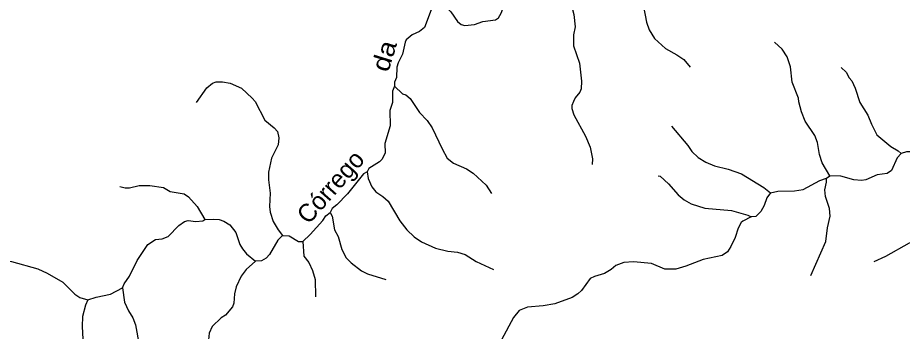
# Model space of a CAD drawing. Extents: x 577 to 602.9, y 7483.8 to 7511.6.
# Drawn here: x 595.283 to 599.238, y 7502.644 to 7504.044 of the extents above; entities that cross this region are included whole.
import ezdxf
from ezdxf.enums import TextEntityAlignment as Align

# ---------------------------------------------------------------- set-up
doc = ezdxf.new("R2010")
doc.units = 0
doc.header["$LTSCALE"] = 0.032
doc.layers.add('61', color=7, linetype='Continuous')
doc.layers.add('7', color=7, linetype='Continuous', lineweight=25)

msp = doc.modelspace()

# ---------------------------------------------------------------- linework, layer by layer
at = {"layer": '7'}
for points in [[(598.1262, 7504.3943), (598.1131, 7504.3706), (598.1057, 7504.3477), (598.1025, 7504.2978), (598.0976, 7504.2749), (598.0861, 7504.2471), (598.0673, 7504.2226), (598.0518, 7504.194), (598.0485, 7504.185), (598.0485, 7504.1597), (598.0812, 7504.0951), (598.0943, 7504.0248), (598.1065, 7503.9905), (598.1303, 7503.9521), (598.1793, 7503.9063), (598.23, 7503.8793), (598.261, 7503.8572), (598.2899, 7503.8234)], [(597.1322, 7504.0796), (597.1698, 7504.0976), (597.1919, 7504.0976), (597.2197, 7504.0714), (597.2491, 7504.0281), (597.2654, 7504.0142), (597.2818, 7504.0093), (597.3259, 7504.0142), (597.3627, 7504.0281), (597.4199, 7504.0346), (597.4322, 7504.0436), (597.4444, 7504.0641), (597.4722, 7504.1401), (597.5008, 7504.1744), (597.536, 7504.1973), (597.5785, 7504.2185), (597.5989, 7504.2234), (597.6488, 7504.2243), (597.6627, 7504.2283), (597.6799, 7504.2382), (597.7248, 7504.2782), (597.7403, 7504.2839)], [(597.7403, 7504.2839), (597.7395, 7504.2635), (597.7314, 7504.2316), (597.7314, 7504.2014), (597.7518, 7504.1589), (597.7592, 7504.0984), (597.769, 7504.0591), (597.7747, 7504.0036), (597.7681, 7503.9676), (597.7673, 7503.9194), (597.7951, 7503.8409), (597.8041, 7503.7616), (597.8017, 7503.7265), (597.7959, 7503.7126), (597.7755, 7503.6872), (597.7673, 7503.6709), (597.7608, 7503.6521), (597.7608, 7503.639), (597.769, 7503.6104), (597.8213, 7503.5156), (597.8425, 7503.4657), (597.8532, 7503.415), (597.852, 7503.3885)], [(597.1322, 7504.0796), (597.102, 7504.0003), (597.0791, 7503.9831), (597.0472, 7503.9684), (597.0202, 7503.9455), (597.0153, 7503.9357), (597.0039, 7503.881), (596.9842, 7503.8434), (596.9785, 7503.8237), (596.9761, 7503.778), (596.9679, 7503.7559), (596.9671, 7503.7387)], [(598.9141, 7503.3382), (598.879, 7503.3962), (598.8676, 7503.433), (598.8594, 7503.4878), (598.8463, 7503.518), (598.803, 7503.5826), (598.7866, 7503.6243), (598.7752, 7503.6684), (598.7736, 7503.6848), (598.7449, 7503.7559), (598.7376, 7503.8254), (598.7237, 7503.8695), (598.7008, 7503.9047), (598.6666, 7503.9345)], [(598.9647, 7503.8222), (598.9861, 7503.8008), (599.0008, 7503.7763), (599.0122, 7503.7632), (599.0278, 7503.7297), (599.0482, 7503.666), (599.0833, 7503.6096), (599.0997, 7503.5687), (599.1242, 7503.5221), (599.1863, 7503.4698), (599.2199, 7503.4502), (599.2329, 7503.4379)], [(596.0828, 7503.6659), (596.1284, 7503.7314), (596.1538, 7503.7518), (596.1701, 7503.7575), (596.1987, 7503.7575), (596.2331, 7503.7518), (596.2837, 7503.7297), (596.332, 7503.6848), (596.3442, 7503.6701), (596.3875, 7503.5867), (596.43, 7503.5532), (596.4448, 7503.5368), (596.4513, 7503.5074), (596.448, 7503.4772), (596.4178, 7503.4167), (596.4039, 7503.3545), (596.4039, 7503.3202), (596.4121, 7503.2605), (596.4096, 7503.2009), (596.4112, 7503.1763), (596.4251, 7503.1338), (596.4472, 7503.0979), (596.4676, 7503.0725)], [(596.9671, 7503.7387), (596.9581, 7503.7167), (596.9589, 7503.6652), (596.9466, 7503.63), (596.9483, 7503.5622), (596.9246, 7503.4821), (596.9254, 7503.4396), (596.9115, 7503.4118), (596.9009, 7503.4011), (596.8535, 7503.3709), (596.8453, 7503.357)], [(596.9671, 7503.7387), (597.0039, 7503.7052), (597.0186, 7503.6995), (597.0374, 7503.6831), (597.0799, 7503.6218), (597.1134, 7503.5859), (597.1363, 7503.5532), (597.1804, 7503.4592), (597.2033, 7503.4167), (597.2319, 7503.3946), (597.29, 7503.3701), (597.3194, 7503.3496), (597.3774, 7503.2973), (597.4007, 7503.2598)], [(599.7365, 7503.6161), (599.707, 7503.603), (599.6163, 7503.594), (599.5893, 7503.5867), (599.5713, 7503.5769), (599.5566, 7503.5622), (599.5509, 7503.5483), (599.5468, 7503.5295), (599.5452, 7503.4788), (599.5386, 7503.4665), (599.5215, 7503.4543), (599.5051, 7503.4518), (599.4651, 7503.46), (599.4438, 7503.4584), (599.4209, 7503.4518), (599.3817, 7503.4306), (599.3539, 7503.424), (599.2722, 7503.4461), (599.2563, 7503.4449), (599.2329, 7503.4379)], [(598.2053, 7503.5604), (598.279, 7503.4739), (598.297, 7503.4469), (598.3256, 7503.4199), (598.3591, 7503.3995), (598.3984, 7503.3832), (598.4589, 7503.3684), (598.5193, 7503.3472), (598.6191, 7503.2867), (598.6485, 7503.2622)], [(599.2329, 7503.4379), (599.215, 7503.4191), (599.1888, 7503.3627), (599.17, 7503.3488), (599.1259, 7503.3423), (599.0744, 7503.321), (599.0547, 7503.3178), (599.0204, 7503.321), (598.9632, 7503.3366), (598.9141, 7503.3382)], [(596.8453, 7503.357), (596.8289, 7503.348), (596.7578, 7503.2573), (596.7096, 7503.2082), (596.6892, 7503.1927), (596.6794, 7503.1747)], [(596.8453, 7503.357), (596.8502, 7503.3267), (596.8657, 7503.2891), (596.8845, 7503.2663), (596.9156, 7503.2466), (596.9401, 7503.2246), (596.9916, 7503.1379), (597.0235, 7503.0971), (597.0562, 7503.066), (597.0889, 7503.0439), (597.151, 7503.0153), (597.2066, 7503.0022), (597.2499, 7502.9973), (597.2842, 7502.9875), (597.3325, 7502.9565), (597.4096, 7502.9205)], [(598.147, 7503.3383), (598.1548, 7503.3366), (598.1924, 7503.303), (598.2357, 7503.254), (598.2627, 7503.2311), (598.2937, 7503.2131), (598.355, 7503.1935), (598.4744, 7503.1837), (598.5479, 7503.1633), (598.5618, 7503.1551)], [(598.6485, 7503.2622), (598.682, 7503.2695), (598.7564, 7503.2712), (598.794, 7503.2777), (598.8684, 7503.3178), (598.8994, 7503.3276)], [(598.8283, 7502.8939), (598.8953, 7503.0447), (598.9035, 7503.1069), (598.915, 7503.1584), (598.9117, 7503.1927), (598.8937, 7503.2466), (598.8921, 7503.2753), (598.8994, 7503.3104), (598.8994, 7503.3276), (598.9141, 7503.3382)], [(595.7395, 7503.2914), (595.7639, 7503.2851), (595.7835, 7503.2851), (595.826, 7503.2957), (595.8742, 7503.2949), (595.9347, 7503.2859), (595.9649, 7503.2679), (596.0279, 7503.2573), (596.0475, 7503.245), (596.0859, 7503.2017), (596.1194, 7503.1428)], [(598.6485, 7503.2622), (598.6321, 7503.2409), (598.6207, 7503.2066), (598.6052, 7503.1788), (598.5831, 7503.1575), (598.5618, 7503.1551)], [(595.7524, 7502.8379), (595.7598, 7502.8567), (595.7835, 7502.8903), (595.8178, 7502.9597), (595.8644, 7503.0317), (595.8995, 7503.0537), (595.9298, 7503.0578), (595.956, 7503.0676), (596.0042, 7503.1159), (596.0295, 7503.1338), (596.045, 7503.1387), (596.0802, 7503.1347), (596.1104, 7503.1379), (596.1194, 7503.1428)], [(596.1194, 7503.1428), (596.1587, 7503.1453), (596.1832, 7503.1428), (596.2044, 7503.1363), (596.2322, 7503.1199), (596.2584, 7503.0848), (596.2764, 7503.0325), (596.2886, 7503.0129), (596.3066, 7502.9908), (596.3467, 7502.9573)], [(596.5576, 7503.0447), (596.5903, 7503.0758), (596.6475, 7503.1396), (596.6614, 7503.16), (596.6794, 7503.1747)], [(596.6794, 7503.1747), (596.6892, 7503.1584), (596.6998, 7503.0971), (596.7153, 7503.0668), (596.7325, 7503.0088), (596.7521, 7502.9728), (596.7734, 7502.9499), (596.8199, 7502.914), (596.8477, 7502.9001), (596.9293, 7502.8752)], [(598.5618, 7503.1551), (598.5242, 7503.1363), (598.5177, 7503.1298), (598.5038, 7503.1052), (598.4899, 7503.0627), (598.4711, 7503.0227), (598.4556, 7502.999), (598.4319, 7502.9834), (598.3469, 7502.9655), (598.2708, 7502.9352), (598.2259, 7502.9213), (598.176, 7502.9221), (598.1164, 7502.9467), (598.0363, 7502.9548), (597.9929, 7502.9516), (597.957, 7502.9385), (597.9357, 7502.9205), (597.9063, 7502.9025), (597.8613, 7502.8894), (597.8425, 7502.8796), (597.8033, 7502.8265), (597.7869, 7502.811), (597.7624, 7502.7954), (597.6839, 7502.7668), (597.6316, 7502.7578), (597.5622, 7502.7521), (597.5254, 7502.7366), (597.4992, 7502.7063), (597.4453, 7502.6066)], [(599.1123, 7502.9565), (599.1643, 7502.9794), (599.2705, 7503.0398), (599.3147, 7503.0562), (599.3547, 7503.0603), (599.3866, 7503.0529), (599.4275, 7503.0513), (599.5174, 7503.0644), (599.573, 7503.0595), (599.7316, 7503.0742), (599.7912, 7503.0701), (599.8901, 7503.0783), (599.9923, 7503.1003), (600.0381, 7503.1144)], [(596.4676, 7503.0725), (596.4464, 7503.0505), (596.4088, 7502.9875), (596.3941, 7502.9704), (596.3736, 7502.9589), (596.3467, 7502.9573)], [(596.4676, 7503.0725), (596.4963, 7503.0709), (596.5388, 7503.0456), (596.5576, 7503.0447)], [(596.5576, 7503.0447), (596.5625, 7502.9802), (596.5845, 7502.9507), (596.6017, 7502.9156), (596.6131, 7502.8755), (596.614, 7502.7983)], [(595.0965, 7502.9686), (595.2554, 7502.9556), (595.3731, 7502.923), (595.4148, 7502.9041), (595.4851, 7502.8633), (595.5391, 7502.8093), (595.5611, 7502.7946), (595.5971, 7502.784)], [(596.3467, 7502.9573), (596.3042, 7502.9197), (596.2829, 7502.8903), (596.26, 7502.8428), (596.2527, 7502.8118), (596.2494, 7502.7693), (596.2429, 7502.7529), (596.2126, 7502.717), (596.193, 7502.7047), (596.1529, 7502.6663), (596.139, 7502.636), (596.1366, 7502.6058), (596.144, 7502.5576), (596.1538, 7502.5355), (596.1668, 7502.5216), (596.1963, 7502.511), (596.2911, 7502.5077), (596.3238, 7502.4979), (596.3508, 7502.4848), (596.3704, 7502.4807)], [(595.5971, 7502.784), (595.6339, 7502.7963), (595.6985, 7502.8093), (595.7524, 7502.8379)], [(595.7524, 7502.8379), (595.7614, 7502.775), (595.7786, 7502.7349), (595.7982, 7502.7047), (595.8096, 7502.6736), (595.8268, 7502.5829), (595.8628, 7502.4709), (595.8742, 7502.4202), (595.8701, 7502.3148), (595.8603, 7502.2494), (595.8587, 7502.1546), (595.853, 7502.0867), (595.8407, 7502.0344), (595.808, 7501.9486), (595.7941, 7501.8865), (595.7851, 7501.8195), (595.7393, 7501.7369), (595.7287, 7501.6952), (595.7353, 7501.6396), (595.763, 7501.5595), (595.7746, 7501.5068)], [(595.5971, 7502.784), (595.5865, 7502.7603), (595.5734, 7502.7096), (595.5718, 7502.6655), (595.5767, 7502.5535), (595.5718, 7502.5183), (595.5579, 7502.4652), (595.5533, 7502.426)]]:
    msp.add_lwpolyline(points, dxfattribs=at)

# ---------------------------------------------------------------- texts
at = {"layer": '61', "width": 1.15}
msp.add_text('da', height=0.08, rotation=72.863, dxfattribs=at).set_placement((596.9595, 7503.8626), align=Align.CENTER)
at = {"layer": '61'}
msp.add_text('Córrego', height=0.08, rotation=48.531, dxfattribs=at).set_placement((596.7115, 7503.2626), align=Align.CENTER)

doc.saveas('drawing.dxf')
